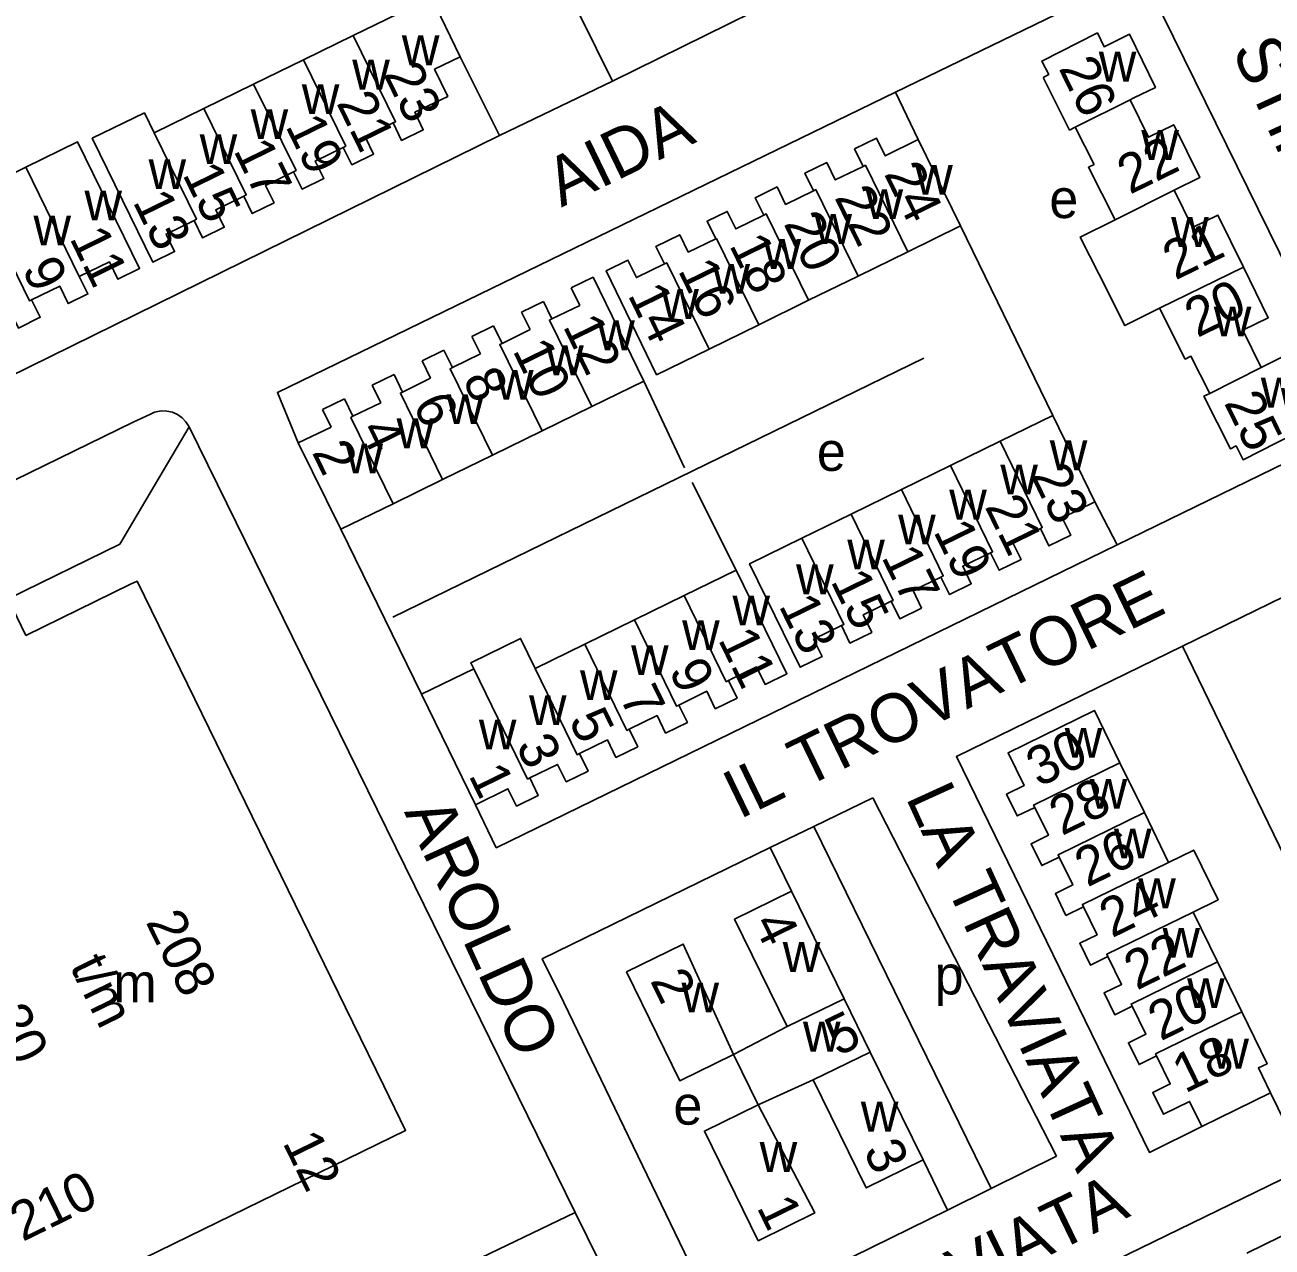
# Model space of a CAD drawing. Extents: x 159441 to 162086, y 388175 to 389787.
# Drawn here: x 161032.2 to 161160.6, y 388881.7 to 389007.5 of the extents above; entities that cross this region are included whole.
import ezdxf

# ---------------------------------------------------------------- set-up
doc = ezdxf.new("R2010")
doc.units = 0
for name, color, linetype in [('BLT_Basislijn', 7, 'Continuous'), ('BLT_Bebouwing', 7, 'Continuous'), ('BLT_Centroide', 7, 'Continuous'), ('BLT_Huisnummer', 7, 'Continuous'), ('BLT_Huisnummer_ tussenligend', 7, 'Continuous'), ('BLT_Huisnummer_reeks', 7, 'Continuous'), ('BLT_Onderverdeling_panden', 7, 'Continuous'), ('BLT_Straatnaam', 7, 'Continuous'), ('BLT_Vlakafsluiter', 7, 'Continuous')]:
    doc.layers.add(name, color=color, linetype=linetype)

msp = doc.modelspace()

# ---------------------------------------------------------------- linework, layer by layer
at = {"layer": 'BLT_Basislijn'}
for p, q in [((161077.03, 389004.24), (161081.07, 388996.12)), ((161070.08, 388946.52), (161124.76, 388973.2)), ((161095.93, 388970.85), (161100.12, 388961.92)), ((161105.44, 388951.38), (161100.91, 388960.41)), ((161151.38, 388943.54), (161168.88, 388907.45)), ((161113.45, 388924.98), (161119.52, 388927.92)), ((161119.52, 388927.92), (161138.43, 388891.03)), ((161108.95, 388922.81), (161113.45, 388924.98)), ((161113.45, 388924.98), (161131.69, 388887.7)), ((161131.69, 388887.7), (161138.43, 388891.03)), ((161127.2, 388885.49), (161131.69, 388887.7)), ((161077.43, 388879.73), (161088.87, 388885.25))]:
    msp.add_line(p, q, dxfattribs=at)
for points in [[(161092.7, 389001.72), (161062.38, 389063.07)], [(161116.67, 389013.57), (161092.7, 389001.72)], [(161147.21, 389012.91), (161121.83, 389000.58)], [(161144.66, 388953.98), (161170.1, 388966.39), (161147.21, 389012.91)], [(161121.83, 389000.58), (161058.2, 388969.68), (161060.33, 388964.47)], [(161121.83, 389000.58), (161124.17, 388995.73)], [(161081.07, 388996.12), (161012.78, 388962.54)], [(161128.53, 388986.82), (161138.03, 388967.29)], [(161049.11, 388966.12), (161048.77, 388966.66), (161048.39, 388967.07), (161047.92, 388967.41), (161047.4, 388967.63), (161046.82, 388967.76), (161046.24, 388967.77), (161045.56, 388967.63), (161045.13, 388967.44), (161043.36, 388966.61), (160999.22, 388945.05), (160996.53, 388943.7)], [(161030.49, 388948.43), (161041.98, 388954.05), (161049.11, 388966.12)], [(161083.97, 388895.22), (161049.11, 388966.12)], [(161142.38, 388958.41), (161144.66, 388953.98)], [(161064.74, 388955.58), (161073.05, 388938.59)], [(161078.59, 388927.22), (161080.73, 388922.8), (161144.66, 388953.98)], [(161163.4, 388949.41), (161151.38, 388943.54)], [(161151.38, 388943.54), (161128.11, 388932.18), (161147.99, 388891.42), (161153.39, 388894.1)], [(161108.95, 388922.81), (161085.48, 388911.35), (161087.68, 388906.85)], [(161111.14, 388918.32), (161108.95, 388922.81)], [(161087.68, 388906.85), (161101.06, 388879.2), (161103.8, 388873.99), (161127.2, 388885.49)], [(161160.47, 388897.55), (161164.2, 388889.91), (161103.74, 388860.46)], [(161088.87, 388885.25), (161083.97, 388895.22)], [(161127.2, 388885.49), (161124.68, 388890.64)], [(161101.91, 388863.83), (161099.9, 388862.83), (161088.87, 388885.25)]]:
    msp.add_lwpolyline(points, dxfattribs=at)
at = {"layer": 'BLT_Bebouwing'}
for p, q in [((161077.03, 389004.24), (161073.76, 389010.99)), ((161066.02, 389006.43), (161060.89, 389003.92)), ((161060.89, 389003.92), (161055.76, 389001.42)), ((161055.76, 389001.42), (161050.63, 388998.92)), ((161146.38, 389000), (161146, 388999.82)), ((161050.63, 388998.92), (161045.51, 388996.41)), ((161128.53, 388986.82), (161124.17, 388995.73)), ((161123.11, 388984.17), (161128.53, 388986.82)), ((161117.99, 388981.66), (161123.11, 388984.17)), ((161088.46, 388980.44), (161090.7, 388981.53)), ((161090.7, 388981.53), (161095.93, 388970.85)), ((161112.89, 388979.16), (161117.99, 388981.66)), ((161089.34, 388978.64), (161088.46, 388980.44)), ((161083.34, 388977.93), (161085.59, 388979.03)), ((161084.22, 388976.14), (161083.34, 388977.93)), ((161085.59, 388979.03), (161086.46, 388977.24)), ((161086.46, 388977.24), (161089.34, 388978.64)), ((161107.77, 388976.65), (161112.89, 388979.16)), ((161102.65, 388974.14), (161107.77, 388976.65)), ((161078.22, 388975.43), (161080.47, 388976.53)), ((161079.1, 388973.64), (161078.22, 388975.43)), ((161080.47, 388976.53), (161081.35, 388974.73)), ((161081.35, 388974.73), (161084.22, 388976.14)), ((161073.1, 388972.93), (161075.35, 388974.03)), ((161073.98, 388971.13), (161073.1, 388972.93)), ((161075.35, 388974.03), (161076.23, 388972.23)), ((161076.23, 388972.23), (161079.1, 388973.64)), ((161067.97, 388970.42), (161070.22, 388971.52)), ((161070.22, 388971.52), (161071.1, 388969.72)), ((161068.85, 388968.62), (161067.97, 388970.42)), ((161071.1, 388969.72), (161073.98, 388971.13)), ((161095.93, 388970.85), (161090.57, 388968.23)), ((161062.86, 388967.92), (161065.1, 388969.01)), ((161065.1, 388969.01), (161065.97, 388967.22)), ((161063.73, 388966.1), (161062.86, 388967.92)), ((161065.97, 388967.22), (161068.85, 388968.62)), ((161138.03, 388967.29), (161132.63, 388964.65)), ((161142.38, 388958.41), (161138.03, 388967.29)), ((161060.33, 388964.47), (161063.73, 388966.1)), ((161132.63, 388964.65), (161127.51, 388962.15)), ((161127.51, 388962.15), (161122.45, 388959.67)), ((161122.45, 388959.67), (161117.27, 388957.14)), ((161117.27, 388957.14), (161112.21, 388954.67)), ((161100.1, 388948.77), (161094.97, 388946.26)), ((161094.97, 388946.26), (161089.87, 388943.76)), ((161089.87, 388943.76), (161084.75, 388941.26)), ((161078.42, 388941.22), (161073.05, 388938.59)), ((161078.59, 388927.22), (161073.05, 388938.59)), ((161144.96, 388931.53), (161147.47, 388926.41)), ((161147.47, 388926.41), (161149.97, 388921.29)), ((161111.14, 388918.32), (161116.56, 388907.24)), ((161152.48, 388916.16), (161154.99, 388911.03)), ((161116.56, 388907.24), (161119.25, 388901.75)), ((161119.25, 388901.75), (161124.68, 388890.64)), ((161160.47, 388897.55), (161153.39, 388894.1))]:
    msp.add_line(p, q, dxfattribs=at)
for points in [[(161073.76, 389010.99), (161070.29, 389009.3), (161070.6, 389008.67), (161066.02, 389006.43)], [(161137.04, 389002.11), (161137.62, 389002.4), (161136.91, 389003.8), (161142.63, 389006.69), (161143.32, 389005.27), (161145.94, 389006.55), (161148.61, 389001.09), (161146.38, 389000)], [(161070.11, 388997.42), (161070.99, 388995.62), (161073.23, 388996.72), (161072.36, 388998.52), (161075.74, 389000.16), (161074.38, 389002.95), (161077.03, 389004.24)], [(161140.36, 388996.99), (161139.77, 388996.69), (161137.04, 389002.11)], [(161146, 388999.82), (161147.88, 388995.96), (161150.49, 388997.24), (161153.17, 388991.79), (161150.55, 388990.51)], [(161045.51, 388996.41), (161044.51, 388998.46), (161039.14, 388995.85), (161045.37, 388983.09), (161047.61, 388984.18), (161046.74, 388985.98), (161049.62, 388987.39)], [(161064.99, 388994.91), (161065.87, 388993.12), (161068.1, 388994.21), (161067.23, 388996.01), (161070.11, 388997.42)], [(161144.45, 388987.44), (161141.71, 388992.86), (161142.29, 388993.16), (161140.36, 388996.99)], [(161037.81, 388981.61), (161040.9, 388983.12), (161041.78, 388981.33), (161044.02, 388982.43), (161037.63, 388995.47), (161032.31, 388992.86)], [(161059.86, 388992.4), (161060.74, 388990.61), (161062.99, 388991.71), (161062.11, 388993.5), (161064.99, 388994.91)], [(161124.17, 388995.73), (161120.78, 388994.04), (161119.89, 388995.85), (161117.64, 388994.75), (161118.52, 388992.95)], [(161118.52, 388992.95), (161115.65, 388991.55), (161114.77, 388993.34), (161112.52, 388992.24), (161113.4, 388990.44)], [(161032.31, 388992.86), (161027.17, 388990.34), (161028.32, 388987.99)], [(161054.74, 388989.89), (161055.61, 388988.1), (161057.86, 388989.2), (161056.98, 388990.99), (161059.86, 388992.4)], [(161113.4, 388990.44), (161110.53, 388989.03), (161109.65, 388990.83), (161107.41, 388989.73), (161108.29, 388987.93)], [(161049.62, 388987.39), (161050.49, 388985.59), (161052.73, 388986.69), (161051.85, 388988.48), (161054.74, 388989.89)], [(161150.55, 388990.51), (161152.43, 388986.67), (161155.04, 388987.94), (161157.66, 388982.59)], [(161108.29, 388987.93), (161105.41, 388986.52), (161104.53, 388988.32), (161102.45, 388987.3), (161103.33, 388985.5)], [(161149.03, 388978.36), (161145.46, 388976.56), (161142.8, 388981.82), (161140.86, 388985.67), (161144.45, 388987.44)], [(161103.33, 388985.5), (161100.51, 388984.12), (161099.63, 388985.91), (161097.17, 388984.71), (161098.05, 388982.92)], [(161098.05, 388982.92), (161095.17, 388981.5), (161094.29, 388983.3), (161092.05, 388982.2), (161097.25, 388971.5), (161102.65, 388974.14)], [(161157.66, 388982.59), (161160.22, 388977.37), (161157.61, 388976.09), (161159.48, 388972.25)], [(161032.9, 388979.21), (161035.79, 388980.62), (161036.67, 388978.83), (161038.69, 388979.82), (161037.81, 388981.61)], [(161027.77, 388976.7), (161030.66, 388978.11), (161031.54, 388976.31), (161033.78, 388977.41), (161032.9, 388979.21)], [(161154.2, 388969.58), (161152.27, 388973.4), (161151.68, 388973.11), (161149.03, 388978.36)], [(161159.48, 388972.25), (161162.1, 388973.53), (161164.77, 388968.07), (161162.14, 388966.78), (161162.84, 388965.37), (161157.64, 388962.74), (161156.92, 388964.16), (161156.34, 388963.86), (161153.61, 388969.29), (161154.2, 388969.58)], [(161090.57, 388968.23), (161085.46, 388965.73)], [(161085.46, 388965.73), (161080.34, 388963.22)], [(161064.74, 388955.58), (161060.33, 388964.47)], [(161080.34, 388963.22), (161075.22, 388960.72)], [(161075.22, 388960.72), (161070.11, 388958.21)], [(161070.11, 388958.21), (161064.74, 388955.58)], [(161136.76, 388955.67), (161137.64, 388953.87), (161139.89, 388954.97), (161139.01, 388956.77), (161142.38, 388958.41)], [(161131.64, 388953.17), (161132.52, 388951.37), (161134.77, 388952.47), (161133.89, 388954.27), (161136.76, 388955.67)], [(161112.21, 388954.67), (161106.82, 388952.04), (161112.04, 388941.37), (161114.28, 388942.47), (161113.41, 388944.26), (161116.28, 388945.67)], [(161126.52, 388950.67), (161127.4, 388948.87), (161129.65, 388949.97), (161128.77, 388951.77), (161131.64, 388953.17)], [(161104.66, 388940), (161107.53, 388941.41), (161108.41, 388939.61), (161110.66, 388940.71), (161105.44, 388951.38), (161100.1, 388948.77)], [(161030.49, 388948.43), (161032.31, 388944.65), (161043.07, 388949.92), (161043.75, 388950.23), (161065.96, 388904.8), (161069.16, 388898.26)], [(161121.4, 388948.17), (161122.28, 388946.37), (161124.52, 388947.47), (161123.65, 388949.27), (161126.52, 388950.67)], [(161116.28, 388945.67), (161117.16, 388943.87), (161119.4, 388944.97), (161118.53, 388946.76), (161121.4, 388948.17)], [(161084.75, 388941.26), (161083.24, 388944.35), (161078.12, 388941.84), (161078.42, 388941.22)], [(161099.54, 388937.49), (161102.41, 388938.9), (161103.29, 388937.1), (161105.54, 388938.2), (161104.66, 388940)], [(161094.43, 388934.99), (161097.3, 388936.4), (161098.18, 388934.6), (161100.42, 388935.7), (161099.54, 388937.49)], [(161136.18, 388926.95), (161134.39, 388926.07), (161133.29, 388928.32), (161135.09, 388929.19), (161133.44, 388932.56), (161142.33, 388936.93), (161144.96, 388931.53)], [(161089.31, 388932.48), (161092.18, 388933.89), (161093.06, 388932.09), (161095.31, 388933.19), (161094.43, 388934.99)], [(161084.19, 388929.98), (161087.06, 388931.38), (161087.94, 388929.59), (161090.19, 388930.69), (161089.31, 388932.48)], [(161078.59, 388927.22), (161081.94, 388928.87), (161082.83, 388927.08), (161085.07, 388928.18), (161084.19, 388929.98)], [(161138.69, 388921.83), (161136.9, 388920.95), (161135.8, 388923.2), (161137.59, 388924.08), (161136.18, 388926.95)], [(161141.2, 388916.71), (161139.4, 388915.83), (161138.31, 388918.08), (161140.1, 388918.96), (161138.69, 388921.83)], [(161149.97, 388921.29), (161152.55, 388922.55), (161155.06, 388917.43), (161152.48, 388916.16)], [(161110.69, 388904.38), (161105.27, 388915.45), (161111.14, 388918.32)], [(161143.71, 388911.58), (161141.92, 388910.7), (161140.82, 388912.95), (161142.61, 388913.83), (161141.2, 388916.71)], [(161105.17, 388901.51), (161099.64, 388898.8), (161094.15, 388910.01), (161099.99, 388912.87), (161105.17, 388901.51)], [(161146.22, 388906.47), (161144.42, 388905.59), (161143.32, 388907.84), (161145.12, 388908.72), (161143.71, 388911.58)], [(161154.99, 388911.03), (161157.49, 388905.9)], [(161148.73, 388901.35), (161146.93, 388900.47), (161145.83, 388902.72), (161147.63, 388903.6), (161146.22, 388906.47)], [(161157.49, 388905.9), (161160.1, 388900.55), (161159.22, 388900.12), (161160.47, 388897.55)], [(161107.71, 388896.33), (161105.17, 388901.51)], [(161153.39, 388894.1), (161152.13, 388896.67), (161149.44, 388895.35), (161148.34, 388897.6), (161150.13, 388898.48), (161148.73, 388901.35)], [(161124.68, 388890.64), (161118.83, 388887.77), (161113.38, 388898.89)], [(161069.16, 388898.26), (161071.4, 388893.68), (161044.56, 388880.55), (161049.92, 388869.55)], [(161107.7, 388882.33), (161102.17, 388893.62), (161107.71, 388896.33)], [(161107.71, 388896.33), (161113.54, 388885.19), (161107.7, 388882.33)], [(161158.02, 388881.04), (161166.63, 388885.26)]]:
    msp.add_lwpolyline(points, dxfattribs=at)
at = {"layer": 'BLT_Onderverdeling_panden'}
for p, q in [((161146, 388999.82), (161140.36, 388996.99)), ((161150.55, 388990.51), (161144.45, 388987.44)), ((161157.66, 388982.59), (161149.03, 388978.36)), ((161159.48, 388972.25), (161154.2, 388969.58)), ((161116.56, 388907.24), (161110.69, 388904.38)), ((161105.17, 388901.51), (161110.69, 388904.38)), ((161113.38, 388898.89), (161119.25, 388901.75)), ((161113.38, 388898.89), (161107.71, 388896.33))]:
    msp.add_line(p, q, dxfattribs=at)
for points in [[(161066.02, 389006.43), (161070.38, 388997.55), (161070.11, 388997.42)], [(161060.89, 389003.92), (161065.24, 388995.04), (161064.99, 388994.91)], [(161055.76, 389001.42), (161060.12, 388992.53), (161059.86, 388992.4)], [(161050.63, 388998.92), (161054.99, 388990.02), (161054.74, 388989.89)], [(161045.51, 388996.41), (161049.87, 388987.51), (161049.62, 388987.39)], [(161032.31, 388992.86), (161037.81, 388981.61)], [(161123.11, 388984.17), (161118.75, 388993.07), (161118.52, 388992.95)], [(161117.99, 388981.66), (161113.64, 388990.56), (161113.4, 388990.44)], [(161028.32, 388987.99), (161032.68, 388979.1), (161032.9, 388979.21)], [(161112.89, 388979.16), (161108.53, 388988.05), (161108.29, 388987.93)], [(161107.77, 388976.65), (161103.41, 388985.54), (161103.33, 388985.5)], [(161102.65, 388974.14), (161098.29, 388983.03), (161098.05, 388982.92)], [(161090.57, 388968.23), (161086.22, 388977.12), (161086.46, 388977.24)], [(161085.46, 388965.73), (161081.1, 388974.61), (161081.35, 388974.73)], [(161080.34, 388963.22), (161075.98, 388972.11), (161076.23, 388972.23)], [(161075.22, 388960.72), (161070.87, 388969.61), (161071.1, 388969.72)], [(161070.11, 388958.21), (161065.75, 388967.11), (161065.97, 388967.22)], [(161132.63, 388964.65), (161136.95, 388955.76), (161136.76, 388955.67)], [(161127.51, 388962.15), (161131.84, 388953.26), (161131.64, 388953.17)], [(161122.45, 388959.67), (161126.77, 388950.79), (161126.52, 388950.67)], [(161117.27, 388957.14), (161121.59, 388948.26), (161121.4, 388948.17)], [(161112.21, 388954.67), (161116.53, 388945.79), (161116.28, 388945.67)], [(161100.1, 388948.77), (161104.42, 388939.88), (161104.66, 388940)], [(161094.97, 388946.26), (161099.3, 388937.37), (161099.54, 388937.49)], [(161089.87, 388943.76), (161094.19, 388934.87), (161094.43, 388934.99)], [(161078.42, 388941.22), (161083.96, 388929.86), (161084.19, 388929.98)], [(161084.75, 388941.26), (161089.08, 388932.37), (161089.31, 388932.48)], [(161144.96, 388931.53), (161136.07, 388927.19), (161136.18, 388926.95)], [(161147.47, 388926.41), (161138.58, 388922.07), (161138.69, 388921.83)], [(161149.97, 388921.29), (161141.09, 388916.94), (161141.2, 388916.71)], [(161152.48, 388916.16), (161143.6, 388911.82), (161143.71, 388911.58)], [(161154.99, 388911.03), (161146.11, 388906.69), (161146.22, 388906.47)], [(161157.49, 388905.9), (161148.62, 388901.57), (161148.73, 388901.35)]]:
    msp.add_lwpolyline(points, dxfattribs=at)
at = {"layer": 'BLT_Vlakafsluiter'}
msp.add_line((161092.7, 389001.72), (161081.07, 388996.12), dxfattribs=at)

# ---------------------------------------------------------------- texts
at = {"layer": 'BLT_Centroide'}
for s, p in [('w', (161071.02, 389003.36)), ('w', (161065.91, 389000.86)), ('w', (161142.78, 389001.69)), ('w', (161060.72, 388998.33)), ('w', (161055.45, 388995.77)), ('w', (161050.2, 388993.19)), ('w', (161147.16, 388993.62)), ('w', (161044.94, 388990.61)), ('w', (161123.88, 388990.03)), ('e', (161137.69, 388987.63)), ('w', (161038.34, 388987.39)), ('w', (161118.77, 388987.53)), ('w', (161033.09, 388984.81)), ('w', (161113.5, 388984.97)), ('w', (161150.23, 388984.66)), ('w', (161108.25, 388982.39)), ('w', (161103, 388979.83)), ('w', (161097.73, 388977.25)), ('w', (161154.62, 388975.45)), ('w', (161091.14, 388974.02)), ('w', (161085.88, 388971.45)), ('w', (161080.72, 388968.92)), ('w', (161159.46, 388968.12)), ('w', (161075.61, 388966.42)), ('w', (161070.48, 388963.92)), ('w', (161065.22, 388961.34)), ('e', (161113.75, 388961.6)), ('w', (161137.73, 388961.67)), ('w', (161132.64, 388959.17)), ('w', (161127.38, 388956.59)), ('w', (161122.12, 388954.02)), ('w', (161116.88, 388951.45)), ('w', (161111.61, 388948.89)), ('w', (161105.06, 388945.69)), ('w', (161099.88, 388943.14)), ('w', (161094.62, 388940.58)), ('w', (161089.36, 388938)), ('w', (161084.11, 388935.42)), ('w', (161078.95, 388932.91)), ('w', (161139.27, 388932.06)), ('w', (161141.84, 388926.81)), ('w', (161144.34, 388921.69)), ('w', (161146.84, 388916.56)), ('w', (161149.34, 388911.47)), ('w', (161110.24, 388910)), ('m', (161041.32, 388906.88)), ('p', (161125.88, 388907.69)), ('w', (161099.81, 388905.83)), ('w', (161151.87, 388906.28)), ('w', (161112.32, 388901.81)), ('w', (161154.37, 388900.06)), ('e', (161098.98, 388894.28)), ('w', (161118.28, 388893.56)), ('w', (161107.86, 388889.41))]:
    msp.add_text(s, height=4, dxfattribs=at).set_placement(p)
at = {"layer": 'BLT_Huisnummer'}
for s, rotation, p in [('23', 296.0661, (161069.08, 389002.48)), ('26', 296.0557, (161138.6, 389003.07)), ('17', 296.0661, (161053.64, 388994.61)), ('24', 296.0557, (161120.62, 388992.2)), ('13', 296.0661, (161043.27, 388989.33)), ('21', 26.0701, (161150.66, 388981.19)), ('11', 296.0661, (161036.76, 388985.57)), ('18', 296.0557, (161104.68, 388984.85)), ('14', 296.0557, (161094.23, 388979.74)), ('12', 296.0557, (161087.55, 388976.52)), ('6', 296.0557, (161072.09, 388968.43)), ('25', 296.0624, (161155.63, 388968.62)), ('2', 296.0557, (161061.71, 388963.53)), ('23', 296.0624, (161135.73, 388961.15)), ('17', 296.0624, (161120.35, 388952.74)), ('13', 296.0624, (161109.78, 388947.73)), ('11', 296.0624, (161103.53, 388944.25)), ('9', 296.0624, (161098.46, 388941.06)), ('5', 296.0624, (161088.15, 388935.93)), ('30', 26.0655, (161136.6, 388928.98)), ('1', 296.0624, (161077.84, 388930.27)), ('26', 26.0655, (161141.6, 388918.69)), ('4', 296.064, (161107.13, 388915.04)), ('22', 26.0655, (161146.68, 388908.07)), ('2', 296.064, (161096.54, 388909.12)), ('5', 26.064, (161115.91, 388901.27)), ('18', 26.0655, (161151.65, 388897.46)), ('3', 296.064, (161118.48, 388891.58)), ('1', 296.064, (161107.51, 388885.79))]:
    msp.add_text(s, height=4, rotation=rotation, dxfattribs=at).set_placement(p)
at = {"layer": 'BLT_Huisnummer_ tussenligend'}
for s, rotation, p in [('21', 296.0661, (161064.24, 388999.49)), ('19', 296.0661, (161058.98, 388997.12)), ('22', 26.0701, (161145.98, 388990.02)), ('15', 296.0661, (161048.38, 388992.15)), ('22', 296.0557, (161115.52, 388989.77)), ('20', 296.0557, (161110.28, 388987.08)), ('9', 296.0661, (161031.86, 388982.4)), ('16', 296.0557, (161099.4, 388982.27)), ('20', 26.0701, (161152.92, 388975.27)), ('10', 296.0557, (161082.38, 388974.01)), ('8', 296.0557, (161077.21, 388971.01)), ('4', 296.0557, (161066.64, 388965.85)), ('21', 296.0624, (161130.99, 388957.93)), ('19', 296.0624, (161125.7, 388955.38)), ('15', 296.0624, (161115.12, 388950.26)), ('7', 296.0624, (161093.38, 388938.32)), ('3', 296.0624, (161082.71, 388933.3)), ('28', 26.0655, (161138.97, 388923.98)), ('24', 26.0655, (161144.13, 388913.46)), ('20', 26.0655, (161149.14, 388902.84))]:
    msp.add_text(s, height=4, rotation=rotation, dxfattribs=at).set_placement(p)
at = {"layer": 'BLT_Huisnummer_reeks'}
for s, rotation, p in [('208', 296.0616, (161044.6, 388915.16)), ('t/m', 296.0616, (161036.79, 388910.61)), ('20', 296.0616, (161028.6, 388905.52)), ('12', 296.0616, (161058.7, 388892.44)), ('210', 26.0616, (161031.97, 388882.19))]:
    msp.add_text(s, height=4, rotation=rotation, dxfattribs=at).set_placement(p)
at = {"layer": 'BLT_Straatnaam'}
for s, rotation, p in [('STIFFELIO', 294.5309, (161156.43, 389004.94)), ('AIDA', 25.8394, (161087.44, 388988.7)), ('IL TROVATORE', 25.8394, (161105.76, 388925.68)), ('LA TRAVIATA', 294.5309, (161122.86, 388927.99)), ('AROLDO', 294.5309, (161071.22, 388926.49)), ('LA TRAVIATA', 25.8394, (161107.72, 388866.29))]:
    msp.add_text(s, height=5, rotation=rotation, dxfattribs=at).set_placement(p)

doc.saveas('drawing.dxf')
